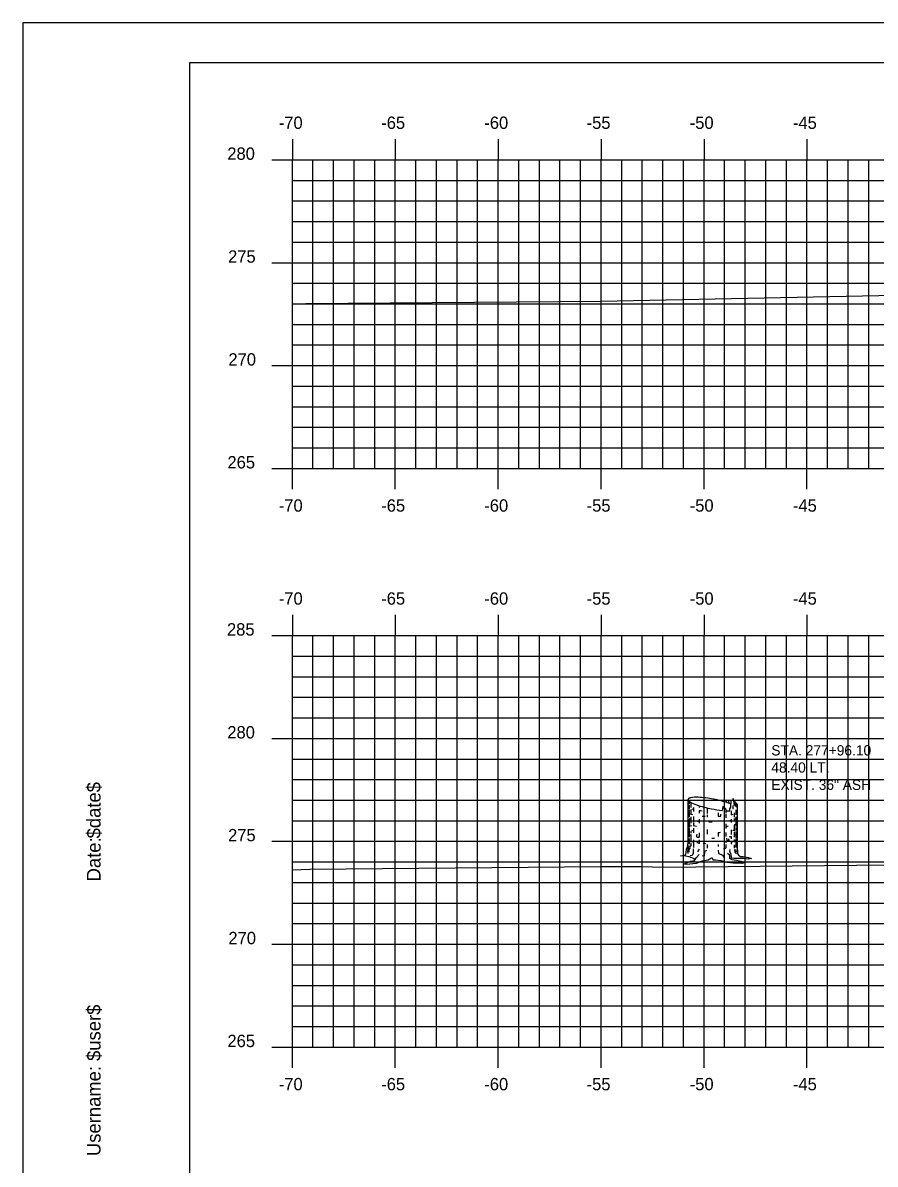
# Model space of a CAD drawing. Extents: x 854453 to 854623, y 366268 to 366378.
# Drawn here: x 854453.3 to 854494.8, y 366322.7 to 366378.2 of the extents above; entities that cross this region are included whole.
import ezdxf

# ---------------------------------------------------------------- set-up
doc = ezdxf.new("R2010")
doc.units = 0
for name, color, linetype in [('BORDER', 7, 'Continuous'), ('D_Text_Monospaced', 7, 'Continuous'), ('H_V ANNOTATION', 7, 'Continuous'), ('MAJOR', 7, 'Continuous'), ('MINOR', 7, 'Continuous'), ('PLOT BOUNDARY', 7, 'Continuous'), ('S_Roadway_Centerline', 7, 'Continuous'), ('S_Trees_Decid_Pay', 7, 'Continuous')]:
    doc.layers.add(name, color=color, linetype=linetype)

msp = doc.modelspace()

# ---------------------------------------------------------------- linework, layer by layer
at = {"layer": 'BORDER'}
for p, q in [((854621.439, 366376.236), (854461.439, 366376.236)), ((854461.439, 366376.236), (854461.439, 366271.236))]:
    msp.add_line(p, q, dxfattribs=at)
at = {"layer": 'MAJOR'}
for p, q in [((854466.439, 366372.523), (854466.439, 366371.521)), ((854471.439, 366372.523), (854471.439, 366371.521)), ((854476.439, 366372.523), (854476.439, 366371.521)), ((854481.439, 366372.523), (854481.439, 366371.521)), ((854486.439, 366372.523), (854486.439, 366371.521)), ((854491.439, 366372.523), (854491.439, 366371.521)), ((854465.437, 366371.521), (854466.439, 366371.521)), ((854466.439, 366371.521), (854606.439, 366371.521)), ((854466.439, 366356.521), (854466.439, 366371.521)), ((854466.439, 366356.521), (854466.439, 366371.521)), ((854471.439, 366356.521), (854471.439, 366371.521)), ((854476.439, 366356.521), (854476.439, 366371.521)), ((854481.439, 366356.521), (854481.439, 366371.521)), ((854486.439, 366356.521), (854486.439, 366371.521)), ((854491.439, 366356.521), (854491.439, 366371.521)), ((854465.437, 366366.521), (854466.439, 366366.521)), ((854466.439, 366366.521), (854606.439, 366366.521)), ((854465.437, 366361.521), (854466.439, 366361.521)), ((854466.439, 366361.521), (854606.439, 366361.521)), ((854465.437, 366356.521), (854466.439, 366356.521)), ((854466.439, 366356.521), (854606.439, 366356.521)), ((854466.439, 366356.521), (854606.439, 366356.521)), ((854466.439, 366355.519), (854466.439, 366356.521)), ((854471.439, 366355.519), (854471.439, 366356.521)), ((854476.439, 366355.519), (854476.439, 366356.521)), ((854481.439, 366355.519), (854481.439, 366356.521)), ((854486.439, 366355.519), (854486.439, 366356.521)), ((854491.439, 366355.519), (854491.439, 366356.521)), ((854466.439, 366349.403), (854466.439, 366348.401)), ((854471.439, 366349.403), (854471.439, 366348.401)), ((854476.439, 366349.403), (854476.439, 366348.401)), ((854481.439, 366349.403), (854481.439, 366348.401)), ((854486.439, 366349.403), (854486.439, 366348.401)), ((854491.439, 366349.403), (854491.439, 366348.401)), ((854465.437, 366348.401), (854466.439, 366348.401)), ((854466.439, 366348.401), (854606.439, 366348.401)), ((854466.439, 366328.401), (854466.439, 366348.401)), ((854466.439, 366328.401), (854466.439, 366348.401)), ((854466.439, 366348.401), (854606.439, 366348.401)), ((854471.439, 366328.401), (854471.439, 366348.401)), ((854476.439, 366328.401), (854476.439, 366348.401)), ((854481.439, 366328.401), (854481.439, 366348.401)), ((854486.439, 366328.401), (854486.439, 366348.401)), ((854491.439, 366328.401), (854491.439, 366348.401)), ((854465.437, 366343.401), (854466.439, 366343.401)), ((854466.439, 366343.401), (854606.439, 366343.401)), ((854465.437, 366338.401), (854466.439, 366338.401)), ((854466.439, 366338.401), (854606.439, 366338.401)), ((854465.437, 366333.401), (854466.439, 366333.401)), ((854466.439, 366333.401), (854606.439, 366333.401)), ((854465.437, 366328.401), (854466.439, 366328.401)), ((854466.439, 366328.401), (854606.439, 366328.401)), ((854466.439, 366328.401), (854606.439, 366328.401)), ((854466.439, 366327.399), (854466.439, 366328.401)), ((854471.439, 366327.399), (854471.439, 366328.401)), ((854476.439, 366327.399), (854476.439, 366328.401)), ((854481.439, 366327.399), (854481.439, 366328.401)), ((854486.439, 366327.399), (854486.439, 366328.401)), ((854491.439, 366327.399), (854491.439, 366328.401))]:
    msp.add_line(p, q, dxfattribs=at)
at = {"layer": 'MINOR'}
for p, q in [((854467.439, 366356.521), (854467.439, 366371.521)), ((854468.439, 366356.521), (854468.439, 366371.521)), ((854469.439, 366356.521), (854469.439, 366371.521)), ((854470.439, 366356.521), (854470.439, 366371.521)), ((854472.439, 366356.521), (854472.439, 366371.521)), ((854473.439, 366356.521), (854473.439, 366371.521)), ((854474.439, 366356.521), (854474.439, 366371.521)), ((854475.439, 366356.521), (854475.439, 366371.521)), ((854477.439, 366356.521), (854477.439, 366371.521)), ((854478.439, 366356.521), (854478.439, 366371.521)), ((854479.439, 366356.521), (854479.439, 366371.521)), ((854480.439, 366356.521), (854480.439, 366371.521)), ((854482.439, 366356.521), (854482.439, 366371.521)), ((854483.439, 366356.521), (854483.439, 366371.521)), ((854484.439, 366356.521), (854484.439, 366371.521)), ((854485.439, 366356.521), (854485.439, 366371.521)), ((854487.439, 366356.521), (854487.439, 366371.521)), ((854488.439, 366356.521), (854488.439, 366371.521)), ((854489.439, 366356.521), (854489.439, 366371.521)), ((854490.439, 366356.521), (854490.439, 366371.521)), ((854492.439, 366356.521), (854492.439, 366371.521)), ((854493.439, 366356.521), (854493.439, 366371.521)), ((854494.439, 366356.521), (854494.439, 366371.521)), ((854466.439, 366370.521), (854606.439, 366370.521)), ((854466.439, 366370.521), (854467.441, 366370.521)), ((854466.439, 366369.521), (854606.439, 366369.521)), ((854466.439, 366369.521), (854467.441, 366369.521)), ((854466.439, 366368.521), (854606.439, 366368.521)), ((854466.439, 366368.521), (854467.441, 366368.521)), ((854466.439, 366367.521), (854606.439, 366367.521)), ((854466.439, 366367.521), (854467.441, 366367.521)), ((854466.439, 366365.521), (854606.439, 366365.521)), ((854466.439, 366365.521), (854467.441, 366365.521)), ((854466.439, 366364.521), (854606.439, 366364.521)), ((854466.439, 366364.521), (854467.441, 366364.521)), ((854466.439, 366363.521), (854606.439, 366363.521)), ((854466.439, 366363.521), (854467.441, 366363.521)), ((854466.439, 366362.521), (854606.439, 366362.521)), ((854466.439, 366362.521), (854467.441, 366362.521)), ((854466.439, 366360.521), (854606.439, 366360.521)), ((854466.439, 366360.521), (854467.441, 366360.521)), ((854466.439, 366359.521), (854606.439, 366359.521)), ((854466.439, 366359.521), (854467.441, 366359.521)), ((854466.439, 366358.521), (854606.439, 366358.521)), ((854466.439, 366358.521), (854467.441, 366358.521)), ((854466.439, 366357.521), (854606.439, 366357.521)), ((854466.439, 366357.521), (854467.441, 366357.521)), ((854467.439, 366328.401), (854467.439, 366348.401)), ((854468.439, 366328.401), (854468.439, 366348.401)), ((854469.439, 366328.401), (854469.439, 366348.401)), ((854470.439, 366328.401), (854470.439, 366348.401)), ((854472.439, 366328.401), (854472.439, 366348.401)), ((854473.439, 366328.401), (854473.439, 366348.401)), ((854474.439, 366328.401), (854474.439, 366348.401)), ((854475.439, 366328.401), (854475.439, 366348.401)), ((854477.439, 366328.401), (854477.439, 366348.401)), ((854478.439, 366328.401), (854478.439, 366348.401)), ((854479.439, 366328.401), (854479.439, 366348.401)), ((854480.439, 366328.401), (854480.439, 366348.401)), ((854482.439, 366328.401), (854482.439, 366348.401)), ((854483.439, 366328.401), (854483.439, 366348.401)), ((854484.439, 366328.401), (854484.439, 366348.401)), ((854485.439, 366328.401), (854485.439, 366348.401)), ((854487.439, 366328.401), (854487.439, 366348.401)), ((854488.439, 366328.401), (854488.439, 366348.401)), ((854489.439, 366328.401), (854489.439, 366348.401)), ((854490.439, 366328.401), (854490.439, 366348.401)), ((854492.439, 366328.401), (854492.439, 366348.401)), ((854493.439, 366328.401), (854493.439, 366348.401)), ((854494.439, 366328.401), (854494.439, 366348.401)), ((854466.439, 366347.401), (854606.439, 366347.401)), ((854466.439, 366347.401), (854467.441, 366347.401)), ((854466.439, 366346.401), (854606.439, 366346.401)), ((854466.439, 366346.401), (854467.441, 366346.401)), ((854466.439, 366345.401), (854606.439, 366345.401)), ((854466.439, 366345.401), (854467.441, 366345.401)), ((854466.439, 366344.401), (854606.439, 366344.401)), ((854466.439, 366344.401), (854467.441, 366344.401)), ((854466.439, 366342.401), (854606.439, 366342.401)), ((854466.439, 366342.401), (854467.441, 366342.401)), ((854466.439, 366341.401), (854606.439, 366341.401)), ((854466.439, 366341.401), (854467.441, 366341.401)), ((854466.439, 366340.401), (854606.439, 366340.401)), ((854466.439, 366340.401), (854467.441, 366340.401)), ((854466.439, 366339.401), (854606.439, 366339.401)), ((854466.439, 366339.401), (854467.441, 366339.401)), ((854466.439, 366337.401), (854606.439, 366337.401)), ((854466.439, 366337.401), (854467.441, 366337.401)), ((854466.439, 366336.401), (854606.439, 366336.401)), ((854466.439, 366336.401), (854467.441, 366336.401)), ((854466.439, 366335.401), (854606.439, 366335.401)), ((854466.439, 366335.401), (854467.441, 366335.401)), ((854466.439, 366334.401), (854606.439, 366334.401)), ((854466.439, 366334.401), (854467.441, 366334.401)), ((854466.439, 366332.401), (854606.439, 366332.401)), ((854466.439, 366332.401), (854467.441, 366332.401)), ((854466.439, 366331.401), (854606.439, 366331.401)), ((854466.439, 366331.401), (854467.441, 366331.401)), ((854466.439, 366330.401), (854606.439, 366330.401)), ((854466.439, 366330.401), (854467.441, 366330.401)), ((854466.439, 366329.401), (854606.439, 366329.401)), ((854466.439, 366329.401), (854467.441, 366329.401))]:
    msp.add_line(p, q, dxfattribs=at)
at = {"layer": 'PLOT BOUNDARY'}
msp.add_lwpolyline([(854453.345, 366268.177), (854623.345, 366268.177), (854623.345, 366378.177), (854453.345, 366378.177)], close=True, dxfattribs=at)
at = {"layer": 'S_Roadway_Centerline'}
for points in [[(854467.091, 366364.541), (854481.432, 366364.645), (854499.682, 366365.016)], [(854466.439, 366337.023), (854467.281, 366337.051), (854481.427, 366337.184), (854483.376, 366337.181), (854484.492, 366337.138), (854498.521, 366337.292)]]:
    msp.add_lwpolyline(points, dxfattribs=at)
at = {"layer": 'S_Trees_Decid_Pay'}
for p, q in [((854485.715, 366340.341), (854485.715, 366340.221)), ((854485.715, 366340.169), (854485.715, 366339.955)), ((854485.795, 366340.297), (854485.795, 366340.043)), ((854485.795, 366339.947), (854485.795, 366339.683)), ((854485.928, 366340.043), (854485.928, 366339.852)), ((854486.2, 366340.13), (854486.2, 366340.043)), ((854486.583, 366340.029), (854486.583, 366339.749)), ((854487.84, 366340.138), (854487.84, 366339.963)), ((854487.989, 366339.938), (854487.989, 366339.683)), ((854485.715, 366339.91), (854485.715, 366339.572)), ((854485.715, 366339.455), (854485.715, 366339.094)), ((854485.795, 366339.586), (854485.795, 366339.278)), ((854485.928, 366339.6), (854485.928, 366339.323)), ((854486.2, 366339.902), (854486.2, 366339.763)), ((854486.2, 366339.477), (854486.2, 366339.286)), ((854486.583, 366339.683), (854486.583, 366339.58)), ((854487.129, 366339.792), (854487.129, 366339.612)), ((854487.256, 366339.62), (854487.25, 366339.726)), ((854487.494, 366339.891), (854487.494, 366339.772)), ((854487.494, 366339.72), (854487.494, 366339.535)), ((854487.755, 366339.889), (854487.755, 366339.684)), ((854487.755, 366339.477), (854487.755, 366339.323)), ((854487.903, 366339.792), (854487.903, 366339.58)), ((854487.903, 366339.515), (854487.903, 366339.366)), ((854487.989, 366339.586), (854487.989, 366339.117)), ((854485.715, 366339.057), (854485.715, 366338.608)), ((854485.795, 366339.189), (854485.795, 366339.123)), ((854485.795, 366338.889), (854485.795, 366338.791)), ((854485.928, 366339.278), (854485.928, 366339.169)), ((854485.928, 366339.034), (854485.928, 366338.806)), ((854486.583, 366338.969), (854486.583, 366338.748)), ((854487.129, 366338.834), (854487.129, 366338.637)), ((854487.494, 366339.249), (854487.494, 366339.02)), ((854487.755, 366338.96), (854487.755, 366338.74)), ((854487.903, 366339.189), (854487.903, 366338.889)), ((854487.903, 366338.851), (854487.903, 366338.608)), ((854487.989, 366339.066), (854487.989, 366338.932)), ((854487.989, 366338.874), (854487.989, 366338.549)), ((854485.715, 366338.543), (854485.715, 366338.261)), ((854485.795, 366338.74), (854485.795, 366338.38)), ((854485.795, 366338.328), (854485.795, 366338.162)), ((854485.928, 366338.476), (854485.928, 366338.093)), ((854486.2, 366338.806), (854486.2, 366338.598)), ((854486.2, 366338.476), (854486.2, 366338.277)), ((854487.494, 366338.822), (854487.494, 366338.637)), ((854487.494, 366338.402), (854487.494, 366338.326)), ((854487.755, 366338.641), (854487.755, 366338.52)), ((854487.755, 366338.369), (854487.755, 366338.27)), ((854487.903, 366338.497), (854487.903, 366338.357)), ((854487.989, 366338.52), (854487.989, 366338.1)), ((854486.204, 366338.02), (854486.124, 366337.888)), ((854486.583, 366338.248), (854486.583, 366338.075)), ((854487.129, 366338.254), (854487.129, 366338.151)), ((854487.494, 366338.248), (854487.494, 366338.075)), ((854487.903, 366338.225), (854487.903, 366338.069)), ((854487.986, 366337.997), (854488, 366337.879))]:
    msp.add_line(p, q, dxfattribs=at)
for points in [[(854488.04, 366340.212), (854488.04, 366338.075), (854488.06, 366337.933), (854488.066, 366337.807), (854488.109, 366337.721), (854488.202, 366337.671), (854488.338, 366337.671), (854488.581, 366337.616), (854488.748, 366337.566), (854488.605, 366337.536), (854488.369, 366337.573), (854488.159, 366337.56), (854487.897, 366337.566), (854487.773, 366337.585), (854487.743, 366337.542), (854487.681, 366337.585), (854487.78, 366337.517), (854488.015, 366337.492), (854488.245, 366337.431), (854488.375, 366337.36), (854488.276, 366337.317), (854487.854, 366337.336), (854487.576, 366337.379), (854487.277, 366337.455), (854486.991, 366337.492), (854486.886, 366337.492), (854486.868, 366337.573), (854486.8, 366337.579), (854486.633, 366337.492), (854486.347, 366337.436), (854486.048, 366337.33), (854485.589, 366337.28), (854485.435, 366337.293), (854485.777, 366337.443), (854485.98, 366337.474), (854485.968, 366337.548), (854485.708, 366337.647), (854485.533, 366337.678), (854485.292, 366337.69), (854485.491, 366337.727), (854485.552, 366337.764), (854485.577, 366337.85), (854485.589, 366338.02), (854485.634, 366338.106), (854485.663, 366338.347), (854485.663, 366340.433)], [(854487.522, 366339.889), (854487.485, 366339.992), (854487.42, 366339.998), (854487.42, 366340.08), (854487.346, 366340.087), (854487.321, 366339.906)], [(854487.661, 366340.251), (854487.64, 366340.358), (854487.508, 366340.389), (854487.501, 366340.301)], [(854487.683, 366339.885), (854487.691, 366340.029), (854487.737, 366340.021), (854487.751, 366340.396), (854487.846, 366340.404), (854487.86, 366340.484), (854487.897, 366340.146), (854487.943, 366340.241), (854487.963, 366340.087), (854488.04, 366340.212), (854488.034, 366340.022)], [(854488.04, 366340.212), (854487.994, 366340.235), (854487.972, 366340.301), (854487.92, 366340.324), (854487.886, 366340.249)], [(854486.086, 366338.612), (854486.088, 366338.688), (854486.096, 366338.755)], [(854487.632, 366338.52), (854487.64, 366338.446), (854487.566, 366338.44), (854487.552, 366338.557)], [(854485.713, 366338.188), (854485.653, 366338.028), (854485.639, 366337.902), (854485.647, 366337.805)], [(854485.77, 366338.108), (854485.699, 366338.005), (854485.699, 366337.879)], [(854485.911, 366338.034), (854485.911, 366337.828), (854485.853, 366337.719), (854485.756, 366337.702)], [(854485.98, 366337.474), (854486.067, 366337.616), (854486.199, 366337.758)], [(854486.565, 366337.959), (854486.462, 366337.908), (854486.448, 366337.702), (854486.345, 366337.673)], [(854487.131, 366337.968), (854487.148, 366337.814), (854487.346, 366337.733), (854487.391, 366337.63)], [(854487.582, 366337.832), (854487.657, 366337.764), (854487.675, 366337.665), (854487.681, 366337.585)], [(854487.773, 366337.585), (854487.755, 366337.764), (854487.693, 366337.9), (854487.7, 366338.001)], [(854487.92, 366338.005), (854487.926, 366337.879), (854488.008, 366337.785)]]:
    msp.add_lwpolyline(points, dxfattribs=at)
for centre, radius, start, end in [((854485.786, 366340.347), 0.164, 110.0157, 124.2221), ((854485.894, 366340.05), 0.48, 101.7221, 110.0157), ((854486.061, 366339.247), 1.299, 86.3056, 101.7221), ((854485.75, 366334.431), 6.126, 79.2221, 86.3056), ((854485.709, 366340.433), 0.0467, 169.2221, 180.9043), ((854485.717, 366340.433), 0.0544, 180.9043, 191.7221), ((854485.717, 366340.106), 0.0554, 191.6815, 202.5), ((854485.709, 366340.433), 0.0467, 157.54, 169.2221), ((854485.727, 366340.435), 0.0645, 191.7221, 204.3989), ((854485.726, 366340.11), 0.0657, 202.5, 215.1737), ((854485.716, 366340.43), 0.0544, 146.7221, 157.54), ((854485.766, 366340.453), 0.107, 204.3989, 214.2221), ((854485.725, 366340.424), 0.0645, 134.0453, 146.7221), ((854485.762, 366340.135), 0.109, 215.1737, 225), ((854485.812, 366340.484), 0.164, 214.2221, 228.4286), ((854485.754, 366340.393), 0.107, 124.2221, 134.0453), ((854485.802, 366340.176), 0.166, 225, 238.33), ((854486.022, 366340.72), 0.48, 228.4286, 236.7221), ((854486.472, 366341.406), 1.299, 236.7221, 252.1387), ((854486.274, 366341.195), 1.292, 250.9084, 254.4349), ((854487.952, 366346), 6.126, 252.1387, 259.2221), ((854487.952, 366346), 6.126, 259.2221, 264.0853), ((854485.75, 366334.431), 6.126, 72.1387, 79.2221), ((854487.23, 366339.025), 1.299, 66.6931, 72.1387), ((854485.718, 366339.845), 0.0554, 191.6815, 202.5), ((854485.727, 366339.849), 0.0657, 202.5, 215.1737), ((854485.763, 366339.874), 0.109, 215.1737, 225), ((854485.803, 366339.915), 0.166, 225, 239.1924), ((854485.803, 366339.651), 0.166, 238.3999, 239.1924), ((854485.966, 366340.188), 0.484, 239.1924, 242.5838), ((854485.966, 366339.924), 0.484, 239.1924, 247.5), ((854486.275, 366340.934), 1.292, 247.5, 251.9171), ((854486.275, 366340.67), 1.292, 247.5, 248.1929), ((854486.275, 366340.67), 1.292, 261.6338, 262.8454), ((854486.851, 366345.258), 5.916, 262.8454, 263.6816), ((854486.85, 366345.783), 5.916, 263.6913, 265.0485), ((854486.851, 366345.522), 5.916, 265.1076, 266.4618), ((854486.851, 366345.522), 5.916, 272.6957, 273.9224), ((854487.952, 366346), 6.126, 265.9754, 266.3056), ((854487.641, 366341.183), 1.299, 266.3056, 271.8711), ((854487.427, 366340.67), 1.292, 280.7368, 284.7144), ((854487.427, 366340.934), 1.292, 284.7144, 289.3881), ((854487.427, 366340.67), 1.292, 291.6463, 292.5), ((854487.736, 366339.924), 0.484, 292.5, 300.8076), ((854487.899, 366339.915), 0.166, 300.8076, 315), ((854487.899, 366339.651), 0.166, 300.8076, 302.9622), ((854487.939, 366339.874), 0.109, 315, 324.8263), ((854487.975, 366339.849), 0.0657, 324.8263, 337.5), ((854487.984, 366339.845), 0.0554, 337.5, 348.3185), ((854487.992, 366339.844), 0.0476, 348.3185, 0), ((854485.718, 366339.324), 0.0554, 191.6815, 202.5), ((854485.718, 366339.067), 0.0554, 191.6815, 202.5), ((854485.727, 366339.328), 0.0657, 202.5, 215.1737), ((854485.727, 366339.071), 0.0657, 202.5, 215.1737), ((854485.763, 366339.353), 0.109, 215.1737, 225), ((854485.763, 366339.096), 0.109, 215.1737, 225), ((854485.803, 366339.394), 0.166, 225, 239.1924), ((854485.803, 366339.136), 0.166, 225, 237.9306), ((854485.966, 366339.667), 0.484, 239.1924, 245.3628), ((854486.275, 366340.156), 1.292, 249.8999, 254.3895), ((854486.275, 366340.413), 1.292, 254.3895, 260.7435), ((854486.851, 366345.258), 5.916, 268.2292, 269.8838), ((854486.851, 366344.744), 5.916, 272.6957, 273.7279), ((854486.851, 366345.001), 5.916, 276.2405, 277.1546), ((854487.427, 366340.413), 1.292, 277.1546, 278.1274), ((854487.427, 366340.156), 1.292, 288.201, 292.5), ((854487.427, 366340.413), 1.292, 291.5158, 292.5), ((854487.736, 366339.667), 0.484, 294.2275, 300.8076), ((854487.899, 366339.394), 0.166, 300.8076, 315), ((854487.899, 366339.136), 0.166, 300.8076, 315), ((854487.939, 366339.353), 0.109, 315, 324.8263), ((854487.939, 366339.096), 0.109, 315, 324.8263), ((854487.975, 366339.328), 0.0657, 324.8263, 337.5), ((854487.975, 366339.071), 0.0657, 324.8263, 337.5), ((854487.984, 366339.324), 0.0554, 337.5, 348.3185), ((854487.984, 366339.067), 0.0554, 337.5, 348.3185), ((854487.992, 366339.323), 0.0476, 348.3185, 0), ((854487.992, 366339.065), 0.0476, 348.3185, 0), ((854485.718, 366338.801), 0.0554, 191.6815, 202.5), ((854485.718, 366338.53), 0.0554, 191.6815, 202.5), ((854485.727, 366338.534), 0.0657, 202.5, 215.1737), ((854485.763, 366338.559), 0.109, 215.1737, 225), ((854485.803, 366338.599), 0.166, 225, 237.9306), ((854485.803, 366338.871), 0.166, 237.9306, 239.1924), ((854485.966, 366339.144), 0.484, 239.1924, 247.5), ((854486.275, 366339.618), 1.292, 250.8466, 254.3895), ((854486.275, 366339.89), 1.292, 261.6205, 262.8454), ((854486.275, 366339.618), 1.292, 261.6338, 262.8454), ((854486.851, 366344.478), 5.916, 262.8454, 263.6816), ((854486.851, 366344.206), 5.916, 262.8454, 263.6816), ((854486.851, 366344.206), 5.916, 265.539, 266.7363), ((854486.851, 366344.478), 5.916, 269.7243, 270), ((854486.851, 366344.478), 5.916, 270, 271.0793), ((854487.427, 366339.89), 1.292, 280.7537, 284.7144), ((854487.427, 366339.618), 1.292, 284.7144, 288.6336), ((854487.427, 366339.89), 1.292, 291.6463, 292.5), ((854487.736, 366339.144), 0.484, 292.5, 300.8076), ((854487.736, 366338.872), 0.484, 292.5, 297.266), ((854487.899, 366338.871), 0.166, 300.8076, 315), ((854487.939, 366338.83), 0.109, 315, 324.8263), ((854487.975, 366338.805), 0.0657, 324.8263, 337.5), ((854487.984, 366338.801), 0.0554, 337.5, 348.3185), ((854487.992, 366338.8), 0.0476, 348.3185, 0), ((854485.966, 366338.615), 0.484, 243.4501, 247.5), ((854486.266, 366339.365), 1.292, 247.9396, 248.6304), ((854486.851, 366343.949), 5.916, 275.2344, 276.2169), ((854487.427, 366339.361), 1.292, 291.6463, 292.5), ((854487.736, 366338.615), 0.484, 292.5, 300.8076), ((854487.899, 366338.342), 0.166, 300.8076, 315), ((854487.939, 366338.301), 0.109, 315, 324.8263), ((854487.975, 366338.276), 0.0657, 324.8263, 337.5), ((854487.984, 366338.272), 0.0554, 337.5, 348.3185), ((854487.992, 366338.271), 0.0476, 348.3185, 0)]:
    msp.add_arc(centre, radius, start, end, dxfattribs=at)

# ---------------------------------------------------------------- texts
at = {"layer": 'BORDER'}
for s, p in [('$date$', (854457.124, 366338.542)), ('Date:', (854457.124, 366336.453)), ('$user$', (854457.124, 366327.728)), ('Username:', (854457.124, 366323.104))]:
    msp.add_text(s, height=0.6696, rotation=90, dxfattribs=at).set_placement(p)
at = {"layer": 'D_Text_Monospaced'}
for s, height, p in [('STA. 277+96.10', 0.49998, (854489.706, 366342.573)), ('48.40 LT.', 0.5, (854489.706, 366341.739)), ('EXIST. 36" ASH', 0.49998, (854489.706, 366340.899))]:
    msp.add_text(s, height=height, dxfattribs=at).set_placement(p)
at = {"layer": 'H_V ANNOTATION'}
for s, p in [('-70', (854465.78, 366373.021)), ('-65', (854470.756, 366373.021)), ('-60', (854475.764, 366373.021)), ('-55', (854480.735, 366373.021)), ('-50', (854485.743, 366373.021)), ('-45', (854490.756, 366373.021)), ('280', (854463.279, 366371.521)), ('275', (854463.317, 366366.521)), ('270', (854463.333, 366361.521)), ('265', (854463.285, 366356.521)), ('-70', (854465.78, 366354.421)), ('-65', (854470.756, 366354.421)), ('-60', (854475.764, 366354.421)), ('-55', (854480.735, 366354.421)), ('-50', (854485.743, 366354.421)), ('-45', (854490.756, 366354.421)), ('-70', (854465.78, 366349.901)), ('-65', (854470.756, 366349.901)), ('-60', (854475.764, 366349.901)), ('-55', (854480.735, 366349.901)), ('-50', (854485.743, 366349.901)), ('-45', (854490.756, 366349.901)), ('285', (854463.263, 366348.401)), ('280', (854463.279, 366343.401)), ('275', (854463.317, 366338.401)), ('270', (854463.333, 366333.401)), ('265', (854463.285, 366328.401)), ('-70', (854465.78, 366326.301)), ('-65', (854470.756, 366326.301)), ('-60', (854475.764, 366326.301)), ('-55', (854480.735, 366326.301)), ('-50', (854485.743, 366326.301)), ('-45', (854490.756, 366326.301))]:
    msp.add_text(s, height=0.6, dxfattribs=at).set_placement(p)
at = {"layer": 'MAJOR'}
for p in [(854466.438, 366356.52), (854466.434, 366328.401)]:
    msp.add_text('-', height=0.00000006, rotation=53.1301, dxfattribs=at).set_placement(p)

doc.saveas('drawing.dxf')
